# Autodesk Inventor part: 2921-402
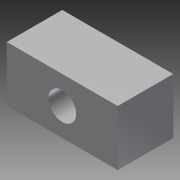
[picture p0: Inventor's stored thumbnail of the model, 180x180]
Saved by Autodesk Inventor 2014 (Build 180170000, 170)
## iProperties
Company: NHTSA/VRTC
Created: 2012-12
Part Number: 2921-402
Material: Steel
Document SubType Name: Modeling
Designer: Mike Vanvoorhis
Density: 7.85 g/cm^3
Mass: 232.019 g
Surface Area: 72.1166 cm^2
Volume: 29.5565 cm^3
Description: ANTI-REBOUND FIXTURE PIVOT BLOCK
Project: CHILD SIDE IMPACT SLED
Stock Number: BAR 25.4 (1.0") x 25.4 (1.0") x 50.8 (2.0")
Appearance: Steel
DESIGN DATE: 2012-11-05
Author: Dave Walker
Title: Anti-Rebound Fixture Pivot Block
Subject: Child Side Inpact Sled
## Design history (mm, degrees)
sketch "Sketch1"
  geometry: L1 (0, 0)-(50.8, 0); L2 (50.8, 0)-(50.8, 25.4); L3 (50.8, 25.4)-(0, 25.4); L4 (0, 25.4)-(0, 0)
  constraints: 8 end point, 2 parallel, 1 horizontal, 1 perpendicular
  dimensions: "d0" = 50.8 distance of L3.end L2.end; "d1" = 25.4 distance of L2.end L1.end
extrude "Extrusion1" new body sketch "Sketch1" stored distance "d2" = 25.4; taper "d3" = 0 deg
sketch "Sketch2"
  geometry: C1 r 6.35 at (25.4, 12.7)
  constraints: 1 centre point
  dimensions: "d4" = 12.7 diameter of C1
hole "Hole1" sketch "Sketch2" at (25.4, 12.7) diameter "d5" = 12.7; stored, may be unused: countersink angle "d9" = 82 deg, drill point angle "d11" = 118 deg; dims "d6" = 19.05, "d7" = 9.525, "d8" = 6.35, "d10" = 25.4
body "Solid1"
